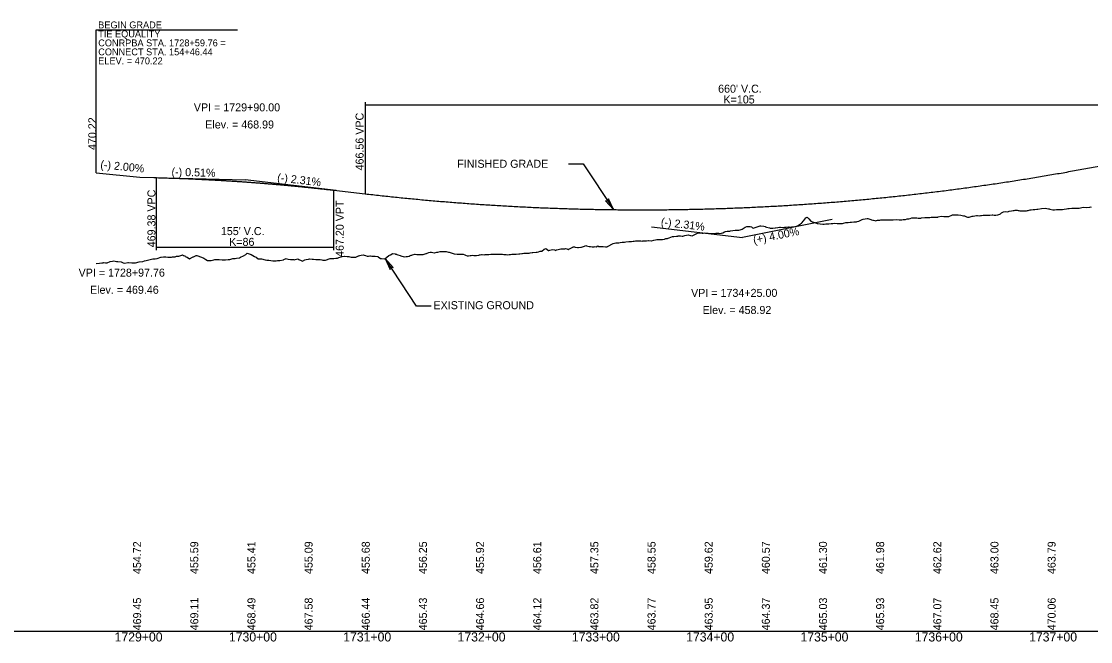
# Model space of a CAD drawing. Extents: x 2017200 to 2047700, y 854850 to 893350.
# Drawn here: x 2020794 to 2021730, y 874091 to 874634 of the extents above; entities that cross this region are included whole.
import ezdxf

# ---------------------------------------------------------------- set-up
doc = ezdxf.new("R2010")
doc.units = 0
for name, color, linetype in [('RD_DDB_GradeTX', 7, 'Continuous'), ('RD_DDB_Profile_EX', 7, 'Continuous'), ('RD_DDB_Profile_Lbl', 7, 'Continuous'), ('RD_DDB_Profile_PR', 7, 'Continuous'), ('RD_DDB_StaTX', 7, 'Continuous'), ('RD_DDB_StripGrade', 7, 'Continuous'), ('RD_DDB_VCLbl', 7, 'Continuous'), ('RD_GPK_Profile_Cell', 7, 'Continuous')]:
    doc.layers.add(name, color=color, linetype=linetype)

msp = doc.modelspace()

# ---------------------------------------------------------------- linework, layer by layer
at = {"layer": 'RD_DDB_GradeTX'}
for p, q in [((2020910.03, 874496.99), (2020990, 874494.95)), ((2021069.47, 874485.75), (2020990, 874494.95)), ((2021503.45, 874460.29), (2021425, 874444.6)), ((2021345.53, 874453.8), (2021425, 874444.6))]:
    msp.add_line(p, q, dxfattribs=at)
at = {"layer": 'RD_DDB_Profile_EX'}
msp.add_lwpolyline([(2020859.76, 874421.68), (2020862.53, 874422.1), (2020864.66, 874422.29), (2020865.68, 874422.32), (2020866.2, 874422.55), (2020867.82, 874422.35), (2020868.83, 874422.45), (2020869.32, 874422.53), (2020871.99, 874423.55), (2020873.98, 874423.83), (2020875.14, 874424.15), (2020877.58, 874423.61), (2020878.29, 874423.52), (2020878.64, 874423.49), (2020881.45, 874423.12), (2020883.3, 874422.28), (2020884.6, 874422.09), (2020887.34, 874422.63), (2020887.95, 874422.77), (2020890.91, 874422.53), (2020892.61, 874422.44), (2020894.06, 874422.4), (2020897.27, 874423.16), (2020900.37, 874423.67), (2020901.93, 874424.27), (2020903.52, 874424.39), (2020906.85, 874425.18), (2020909.1, 874425.75), (2020909.83, 874425.95), (2020911.25, 874425.93), (2020912.98, 874426.06), (2020916.13, 874427.25), (2020916.61, 874427.33), (2020918.63, 874427.49), (2020919.29, 874427.65), (2020920.57, 874427.63), (2020922.44, 874427.41), (2020925.23, 874427.39), (2020925.59, 874427.42), (2020926.37, 874427.49), (2020928.75, 874427.63), (2020929.88, 874428.22), (2020931.9, 874428.16), (2020934.54, 874429.05), (2020935.05, 874429.28), (2020936.12, 874428.89), (2020937.7, 874428.33), (2020938.21, 874427.75), (2020939.2, 874427.2), (2020941.36, 874425.95), (2020943.86, 874427.31), (2020944.51, 874427.5), (2020944.85, 874427.7), (2020945.88, 874428.24), (2020947.23, 874428.76), (2020947.67, 874428.71), (2020948.52, 874428.64), (2020950.82, 874427.6), (2020953.18, 874426.76), (2020953.97, 874426.51), (2020955.64, 874425.39), (2020957.13, 874424.39), (2020957.84, 874424.37), (2020960.28, 874424.46), (2020962.5, 874425.11), (2020963.43, 874425.21), (2020965.4, 874425.3), (2020966.59, 874425.26), (2020967.16, 874425.25), (2020969.74, 874424.89), (2020971.81, 874424.9), (2020972.89, 874424.89), (2020975.16, 874425.24), (2020976.05, 874425.32), (2020976.47, 874425.42), (2020979.2, 874426.05), (2020981.13, 874426.23), (2020982.35, 874426.45), (2020984.91, 874426.9), (2020985.79, 874427.22), (2020988.66, 874428.58), (2020990.45, 874429.54), (2020991.81, 874430.7), (2020995.11, 874429.69), (2020998.12, 874427.87), (2020999.77, 874427.23), (2021001.27, 874426.01), (2021004.43, 874425.85), (2021007.58, 874425.15), (2021009.09, 874424.75), (2021010.73, 874424.77), (2021014.19, 874424.25), (2021017.04, 874424.19), (2021018.4, 874424.29), (2021020.19, 874424.5), (2021023.49, 874425.04), (2021023.94, 874425.27), (2021025.88, 874426.07), (2021026.5, 874425.86), (2021027.72, 874425.6), (2021029.65, 874425.27), (2021032.38, 874425.19), (2021032.81, 874425.12), (2021033.7, 874425.39), (2021035.96, 874425.81), (2021037.04, 874425.34), (2021039.11, 874424.32), (2021040.18, 874423.76), (2021042.27, 874425.09), (2021043.46, 874425.44), (2021045.42, 874425.58), (2021046.36, 874425.81), (2021048.57, 874425.66), (2021049.71, 874425.51), (2021051.73, 874425.25), (2021052.17, 874425.24), (2021053.21, 874425.22), (2021054.88, 874425.2), (2021055.69, 874425.17), (2021057.09, 874424.89), (2021058.04, 874424.7), (2021059.55, 874424.78), (2021060.42, 874424.83), (2021061.21, 874424.98), (2021062.02, 874425.27), (2021062.75, 874425.53), (2021064.48, 874426.15), (2021065.21, 874426.08), (2021066.94, 874426.07), (2021067.55, 874426.06), (2021069.4, 874426.34), (2021070.07, 874426.44), (2021070.72, 874426.5), (2021071.94, 874426.98), (2021073.9, 874427.78), (2021074.33, 874427.85), (2021074.99, 874427.95), (2021076.79, 874428.19), (2021077.09, 874428.23), (2021079.25, 874427.98), (2021079.97, 874427.9), (2021080.28, 874427.8), (2021080.82, 874427.82), (2021081.71, 874427.59), (2021082.77, 874427.31), (2021083.48, 874427.35), (2021084.18, 874427.4), (2021085.03, 874427.46), (2021086.68, 874427.39), (2021089.1, 874428.43), (2021089.43, 874428.57), (2021090.17, 874428.83), (2021091.56, 874429.13), (2021093.1, 874429.45), (2021094.03, 874429.13), (2021095.38, 874428.66), (2021096.73, 874428.26), (2021097.79, 874428.32), (2021099.04, 874428.38), (2021099.54, 874428.44), (2021100.67, 874428.28), (2021101.41, 874428.27), (2021102.76, 874428.25), (2021103.87, 874428.14), (2021106, 874427.96), (2021106.34, 874427.71), (2021108.28, 874426.29), (2021108.8, 874426.19), (2021109.24, 874426.11), (2021111.53, 874425.9), (2021112.48, 874426.14), (2021113.83, 874427.32), (2021115.73, 874428.94), (2021116.19, 874429.09), (2021117.1, 874429.39), (2021118.65, 874430.29), (2021118.99, 874430.49), (2021121.11, 874430.12), (2021121.55, 874430.04), (2021122.25, 874429.88), (2021122.77, 874429.77), (2021123.57, 874429.47), (2021125.52, 874428.75), (2021126.04, 874428.6), (2021129.1, 874427.74), (2021130.96, 874427.83), (2021132.07, 874427.89), (2021133.42, 874428.33), (2021134.44, 874428.66), (2021135.36, 874429.02), (2021135.88, 874429.16), (2021136.47, 874429.32), (2021138.35, 874429.94), (2021138.65, 874430.04), (2021140.24, 874429.73), (2021140.81, 874429.72), (2021141.95, 874429.69), (2021143.27, 874429.73), (2021143.7, 874429.74), (2021145.25, 874429.66), (2021145.73, 874429.8), (2021146.61, 874430.06), (2021148.2, 874430.55), (2021148.57, 874430.66), (2021149.27, 874430.95), (2021150.77, 874431.53), (2021151.89, 874431.83), (2021153.12, 874431.59), (2021155.21, 874431.01), (2021155.58, 874431.1), (2021157.71, 874431.59), (2021158.04, 874431.62), (2021158.55, 874431.66), (2021160.52, 874432.35), (2021161.89, 874432.18), (2021162.97, 874432.27), (2021164.52, 874432.4), (2021165.43, 874432.36), (2021165.94, 874432.27), (2021167.89, 874431.85), (2021168.59, 874431.7), (2021170.36, 874431.05), (2021171.21, 874430.73), (2021171.95, 874430.47), (2021172.82, 874430.34), (2021175.32, 874430.01), (2021177.78, 874430), (2021178.7, 874430.02), (2021180.21, 874429.95), (2021180.61, 874429.93), (2021182.09, 874429.42), (2021182.67, 874429.21), (2021184.25, 874428.61), (2021185.13, 874428.47), (2021185.48, 874428.42), (2021186.88, 874428.75), (2021187.59, 874428.87), (2021188.88, 874429.09), (2021190.05, 874428.91), (2021190.61, 874428.82), (2021192.52, 874428.86), (2021194.29, 874429.16), (2021194.98, 874429.29), (2021195.71, 874429.43), (2021196.88, 874429.55), (2021197.44, 874429.55), (2021199.14, 874429.53), (2021199.9, 874429.59), (2021201.96, 874429.75), (2021202.57, 874429.77), (2021203.05, 874429.79), (2021204.83, 874429.9), (2021206.02, 874429.98), (2021207.29, 874429.98), (2021209.14, 874429.99), (2021209.92, 874429.97), (2021212.21, 874429.93), (2021212.93, 874429.91), (2021214.68, 874429.85), (2021215.14, 874429.83), (2021216.4, 874429.8), (2021217.14, 874429.71), (2021218.2, 874429.59), (2021219.88, 874429.45), (2021221.06, 874429.65), (2021222.06, 874429.82), (2021223.38, 874430.03), (2021224.53, 874429.99), (2021226.99, 874429.91), (2021229.45, 874430.19), (2021230.39, 874430.3), (2021231.91, 874430.5), (2021232.67, 874430.59), (2021233.9, 874430.8), (2021234.38, 874430.8), (2021235.89, 874430.81), (2021236.84, 874430.84), (2021237.43, 874430.87), (2021238.37, 874430.97), (2021239.3, 874431.13), (2021240.97, 874431.42), (2021241.76, 874431.45), (2021244.52, 874431.75), (2021245.44, 874431.85), (2021246.69, 874432.15), (2021248.09, 874432.5), (2021249.15, 874432.67), (2021249.57, 874432.74), (2021251.66, 874434.22), (2021253.01, 874435.01), (2021254.07, 874434.13), (2021255.24, 874433.28), (2021255.56, 874433.31), (2021256.54, 874433.55), (2021259, 874434.1), (2021260.51, 874433.85), (2021261.67, 874433.28), (2021262.44, 874433.74), (2021263.92, 874434.11), (2021266.06, 874434.57), (2021266.38, 874434.61), (2021268.85, 874434.66), (2021269.68, 874434.68), (2021270.31, 874435.01), (2021271.31, 874434.51), (2021272.47, 874433.99), (2021273.32, 874434.5), (2021273.77, 874434.74), (2021276.51, 874436.19), (2021276.98, 874436.28), (2021278.07, 874436.26), (2021278.7, 874436.18), (2021280.64, 874435.93), (2021281.16, 874435.9), (2021281.73, 874435.86), (2021283.62, 874436.12), (2021284.32, 874436.22), (2021286.08, 874436.77), (2021286.9, 874437.02), (2021288.01, 874437.42), (2021288.55, 874437.27), (2021291.01, 874436.63), (2021291.71, 874436.6), (2021292.02, 874436.59), (2021293.47, 874436.5), (2021295.43, 874436.37), (2021296.14, 874436.61), (2021297.1, 874436.46), (2021298.39, 874437.22), (2021299.16, 874436.75), (2021300.86, 874436.7), (2021302.13, 874436.66), (2021302.9, 874436.65), (2021303.32, 874436.6), (2021305.23, 874436.41), (2021305.78, 874436.43), (2021306.66, 874436.46), (2021307.12, 874436.6), (2021308.24, 874437.3), (2021310.71, 874438.74), (2021312.06, 874439.2), (2021313.17, 874439.57), (2021314.22, 874439.91), (2021315.63, 874439.95), (2021316.96, 874439.98), (2021318.09, 874440.09), (2021319.69, 874440.48), (2021320.55, 874440.51), (2021321.85, 874440.55), (2021323.02, 874440.69), (2021325.66, 874441), (2021326.65, 874440.92), (2021327.94, 874441.07), (2021329.51, 874441.24), (2021330.4, 874441.41), (2021331.43, 874441.6), (2021332.87, 874441.61), (2021333.37, 874441.62), (2021335.33, 874441.54), (2021336.18, 874441.5), (2021337.25, 874441.48), (2021337.79, 874441.51), (2021340.25, 874441.65), (2021341.14, 874441.71), (2021342.71, 874441.88), (2021343.16, 874441.93), (2021345.18, 874441.7), (2021345.57, 874441.71), (2021347.64, 874442.17), (2021348.98, 874442.47), (2021350.21, 874442.82), (2021352.56, 874442.9), (2021352.93, 874442.92), (2021355.03, 874442.79), (2021356.89, 874442.97), (2021357.49, 874443.3), (2021358.06, 874443.62), (2021359.4, 874443.71), (2021359.95, 874443.97), (2021360.87, 874444.39), (2021362.41, 874444.93), (2021363.95, 874445.46), (2021364.88, 874445.41), (2021367.34, 874445.69), (2021368.46, 874445.81), (2021368.89, 874445.9), (2021369.8, 874445.99), (2021370.81, 874446.09), (2021372.26, 874445.79), (2021372.95, 874445.65), (2021374.72, 874446.23), (2021377.4, 874447.01), (2021379.65, 874446.45), (2021381.06, 874446.1), (2021382.11, 874446.49), (2021384.57, 874447.84), (2021385.16, 874448.16), (2021386.23, 874448.5), (2021387.04, 874448.54), (2021389.5, 874448.57), (2021389.92, 874448.45), (2021390.6, 874448.35), (2021392.05, 874448.63), (2021393.42, 874448.39), (2021394.42, 874448.31), (2021394.95, 874448.26), (2021396.88, 874448.15), (2021397.58, 874448.11), (2021399.35, 874448.06), (2021401.81, 874448.25), (2021403.57, 874448.31), (2021404.27, 874448.22), (2021405.97, 874448), (2021406.73, 874448.28), (2021407.84, 874448.67), (2021409.2, 874449.54), (2021410.2, 874449.76), (2021411.66, 874450), (2021412.09, 874450.07), (2021414.12, 874450.23), (2021414.45, 874450.26), (2021416.58, 874450.54), (2021418.73, 874450.86), (2021419.05, 874450.89), (2021420.51, 874451.01), (2021421.75, 874451.05), (2021423.03, 874451.36), (2021423.97, 874451.69), (2021424.69, 874451.94), (2021426.43, 874453.09), (2021427.36, 874453.7), (2021428.89, 874454.25), (2021431.36, 874454.06), (2021431.72, 874454.04), (2021432.98, 874453.76), (2021433.82, 874453.16), (2021434.49, 874452.68), (2021436.28, 874453.36), (2021437.09, 874453.51), (2021438.74, 874454.11), (2021440.5, 874454.75), (2021441.21, 874454.85), (2021443.67, 874454.33), (2021444.94, 874454.07), (2021445.25, 874453.96), (2021446.13, 874453.72), (2021448.59, 874453.05), (2021449.4, 874452.85), (2021451.05, 874452.84), (2021451.48, 874452.84), (2021453.52, 874452.98), (2021453.9, 874453.01), (2021455.98, 874453.33), (2021457.35, 874453.55), (2021458.44, 874453.6), (2021460.9, 874453.33), (2021461.35, 874453.29), (2021462.11, 874453.55), (2021462.97, 874453.66), (2021463.37, 874453.68), (2021465.32, 874453.79), (2021465.83, 874453.75), (2021467.56, 874453.63), (2021468.29, 874453.77), (2021469.28, 874453.96), (2021470.75, 874454.26), (2021472.18, 874454.55), (2021473.22, 874454.91), (2021475.68, 874456.42), (2021476.83, 874457.12), (2021477.15, 874457.54), (2021478.14, 874458.75), (2021478.76, 874459.5), (2021480.6, 874461.66), (2021481.52, 874462.41), (2021483.06, 874460.8), (2021484.94, 874458.85), (2021485.53, 874458.53), (2021486.24, 874458.15), (2021487.99, 874457.69), (2021488.82, 874457.47), (2021490.45, 874456.93), (2021491, 874456.75), (2021492.91, 874456.49), (2021495.38, 874456.34), (2021495.79, 874456.32), (2021496.52, 874456.28), (2021497.84, 874456.37), (2021499.29, 874456.47), (2021500.62, 874456.55), (2021502.76, 874456.78), (2021504.15, 874456.94), (2021505.5, 874456.96), (2021507.95, 874456.9), (2021510.41, 874456.91), (2021511.16, 874456.83), (2021511.73, 874456.73), (2021512.61, 874456.94), (2021513.3, 874457.11), (2021515.5, 874457.6), (2021515.91, 874457.63), (2021517.54, 874457.81), (2021519.25, 874458), (2021520, 874458.05), (2021520.36, 874458.07), (2021522.46, 874458.2), (2021522.99, 874458.23), (2021524.92, 874458.41), (2021525.41, 874458.45), (2021526.72, 874458.79), (2021527.39, 874459.11), (2021529.85, 874460.31), (2021530.5, 874460.61), (2021532.31, 874460.93), (2021534.13, 874461.25), (2021534.77, 874461.1), (2021535.63, 874460.9), (2021537.23, 874460.33), (2021537.82, 874460.12), (2021539.06, 874459.7), (2021539.7, 874459.63), (2021540.82, 874459.5), (2021541.49, 874459.27), (2021542.16, 874459.42), (2021543.07, 874459.62), (2021544.62, 874459.79), (2021545.15, 874459.85), (2021546.06, 874459.89), (2021547.08, 874459.89), (2021548.8, 874459.9), (2021549.55, 874459.92), (2021551.35, 874459.95), (2021552.01, 874459.97), (2021552.44, 874459.98), (2021554.77, 874459.98), (2021556.07, 874459.98), (2021556.93, 874460.05), (2021559.68, 874460.17), (2021562.09, 874460.03), (2021563.28, 874460.08), (2021564.32, 874460.16), (2021565.58, 874460.26), (2021567.14, 874460.37), (2021567.55, 874460.43), (2021569.24, 874460.75), (2021570.45, 874460.97), (2021571.71, 874461.29), (2021573.07, 874461.64), (2021574.17, 874461.77), (2021575.71, 874461.75), (2021576.63, 874461.77), (2021577.58, 874461.79), (2021578.65, 874461.58), (2021579.09, 874461.59), (2021581.13, 874461.62), (2021581.55, 874461.67), (2021584.66, 874462.01), (2021585.25, 874462.04), (2021586.48, 874462.08), (2021588.19, 874462.12), (2021588.94, 874462.17), (2021590.02, 874462.25), (2021591.4, 874462.31), (2021591.71, 874462.32), (2021593.87, 874462.26), (2021594.31, 874462.25), (2021595.21, 874462.32), (2021595.81, 874462.46), (2021596.33, 874462.61), (2021598.79, 874463.26), (2021601.25, 874462.9), (2021601.67, 874462.84), (2021602.2, 874462.8), (2021602.95, 874462.8), (2021603.72, 874462.83), (2021605.68, 874462.9), (2021606.18, 874463.14), (2021607.62, 874463.83), (2021608.64, 874464.29), (2021609.15, 874464.52), (2021611.23, 874464.44), (2021612.61, 874464.37), (2021613.64, 874464.29), (2021616.06, 874464.15), (2021618.49, 874463.56), (2021619.18, 874463.39), (2021619.75, 874463.22), (2021620.95, 874462.71), (2021621.79, 874462.35), (2021622.93, 874462.33), (2021623.41, 874462.46), (2021625.95, 874463.12), (2021626.36, 874463.23), (2021626.85, 874463.25), (2021628.34, 874463.53), (2021629.77, 874463.8), (2021630.8, 874463.73), (2021632.24, 874463.62), (2021633.26, 874463.71), (2021634.27, 874463.89), (2021635.72, 874463.99), (2021636.58, 874464.05), (2021638.19, 874464.18), (2021638.63, 874464.22), (2021639.97, 874464.15), (2021640.65, 874464.18), (2021641.45, 874464.21), (2021643.36, 874464.36), (2021643.96, 874464.37), (2021645.12, 874464.19), (2021645.57, 874464.15), (2021646.73, 874464.05), (2021648.04, 874464.38), (2021648.43, 874464.48), (2021650.1, 874465.05), (2021650.65, 874465.21), (2021651.73, 874466.06), (2021652.96, 874466.72), (2021653.46, 874466.99), (2021655.42, 874467.27), (2021656.82, 874467.09), (2021657.89, 874467.34), (2021658.45, 874467.47), (2021660.35, 874467.81), (2021661.81, 874468.07), (2021662.81, 874468.27), (2021663.5, 874468.41), (2021665.29, 874468.34), (2021666.33, 874468.28), (2021666.83, 874468.21), (2021667.73, 874468), (2021668.58, 874467.8), (2021670.2, 874467.89), (2021670.83, 874467.94), (2021672.27, 874467.81), (2021672.66, 874467.83), (2021673.47, 874467.86), (2021674.54, 874468.08), (2021675.12, 874468.24), (2021676.78, 874468.69), (2021677.58, 874468.79), (2021679.38, 874469), (2021680.09, 874469.06), (2021680.69, 874469.13), (2021682.51, 874469.33), (2021683.39, 874469.43), (2021686.74, 874470), (2021689.98, 874470.12), (2021692.78, 874469.59), (2021693.27, 874469.5), (2021693.87, 874469.35), (2021696.57, 874468.82), (2021697.99, 874468.88), (2021699.87, 874468.93), (2021701.12, 874468.98), (2021703.16, 874469.05), (2021704.87, 874469.11), (2021706.46, 874469.24), (2021708.37, 874469.63), (2021709.75, 874469.9), (2021710.91, 874469.83), (2021713.05, 874470.09), (2021715.62, 874470.25), (2021716.35, 874470.36), (2021716.95, 874470.32), (2021719.64, 874470.24), (2021723, 874471.2), (2021726.23, 874470.92), (2021729.04, 874471.2), (2021729.53, 874471.25), (2021730.12, 874471.21)], dxfattribs=at)
at = {"layer": 'RD_DDB_Profile_Lbl'}
for p, q in [((2021139.94, 874384.43), (2021112.48, 874426.14)), ((2021152.8, 874384.43), (2021139.94, 874384.43))]:
    msp.add_line(p, q, dxfattribs=at)
for points in [[(2020859.76, 874501.1), (2020859.76, 874626.27), (2020983.31, 874626.27)], [(2021272.87, 874509.12), (2021285.73, 874509.12), (2021312.18, 874468.94)]]:
    msp.add_lwpolyline(points, dxfattribs=at)
for points in [[(2021312.18, 874468.94), (2021307.72, 874478.44), (2021307.35, 874476.28), (2021305.22, 874476.79)], [(2021112.48, 874426.14), (2021116.94, 874416.64), (2021117.31, 874418.8), (2021119.44, 874418.29)]]:
    msp.add_lwpolyline(points, close=True, dxfattribs=at)
at = {"layer": 'RD_DDB_Profile_PR'}
for p, q in [((2020859.76, 874501.1), (2020897.76, 874497.3)), ((2020897.76, 874497.3), (2020912.5, 874496.92)), ((2021067.5, 874485.98), (2021095, 874482.8))]:
    msp.add_line(p, q, dxfattribs=at)
for points in [[(2021095, 874482.8), (2021108.2, 874481.31), (2021121.4, 874479.91), (2021134.6, 874478.59), (2021147.8, 874477.35), (2021161, 874476.2), (2021174.2, 874475.13), (2021187.4, 874474.14), (2021200.6, 874473.24), (2021213.8, 874472.42), (2021227, 874471.69), (2021240.2, 874471.03), (2021253.4, 874470.46), (2021266.6, 874469.98), (2021279.8, 874469.58), (2021293, 874469.26), (2021306.2, 874469.02), (2021319.4, 874468.87), (2021332.6, 874468.8), (2021345.8, 874468.81), (2021359, 874468.91), (2021372.2, 874469.09), (2021385.4, 874469.36), (2021398.6, 874469.7), (2021411.8, 874470.13), (2021425, 874470.65), (2021438.2, 874471.25), (2021451.4, 874471.93), (2021464.6, 874472.69), (2021477.8, 874473.54), (2021491, 874474.47), (2021504.2, 874475.49), (2021517.4, 874476.58), (2021530.6, 874477.77), (2021543.8, 874479.03), (2021557, 874480.38), (2021570.2, 874481.81), (2021583.4, 874483.32), (2021596.6, 874484.92), (2021609.8, 874486.6), (2021623, 874488.37), (2021636.2, 874490.22), (2021649.4, 874492.15), (2021662.6, 874494.16), (2021675.8, 874496.26), (2021689, 874498.44), (2021702.2, 874500.71), (2021715.4, 874503.06), (2021728.6, 874505.49), (2021741.8, 874508), (2021755, 874510.6)], [(2020912.5, 874496.92), (2020915.6, 874496.84), (2020918.7, 874496.76), (2020921.8, 874496.66), (2020924.9, 874496.56), (2020928, 874496.46), (2020931.1, 874496.35), (2020934.2, 874496.23), (2020937.3, 874496.11), (2020940.4, 874495.99), (2020943.5, 874495.85), (2020946.6, 874495.72), (2020949.7, 874495.57), (2020952.8, 874495.42), (2020955.9, 874495.27), (2020959, 874495.11), (2020962.1, 874494.94), (2020965.2, 874494.77), (2020968.3, 874494.6), (2020971.4, 874494.41), (2020974.5, 874494.23), (2020977.6, 874494.03), (2020980.7, 874493.83), (2020983.8, 874493.63), (2020986.9, 874493.42), (2020990, 874493.2), (2020993.1, 874492.98), (2020996.2, 874492.75), (2020999.3, 874492.52), (2021002.4, 874492.28), (2021005.5, 874492.04), (2021008.6, 874491.79), (2021011.7, 874491.53), (2021014.8, 874491.27), (2021017.9, 874491), (2021021, 874490.73), (2021024.1, 874490.45), (2021027.2, 874490.17), (2021030.3, 874489.88), (2021033.4, 874489.59), (2021036.5, 874489.29), (2021039.6, 874488.98), (2021042.7, 874488.67), (2021045.8, 874488.35), (2021048.9, 874488.03), (2021052, 874487.7), (2021055.1, 874487.37), (2021058.2, 874487.03), (2021061.3, 874486.69), (2021064.4, 874486.34), (2021067.5, 874485.98)]]:
    msp.add_spline(points, degree=3, dxfattribs=at)
at = {"layer": 'RD_DDB_VCLbl'}
for p, q in [((2021095, 874563.1), (2021095, 874482.8)), ((2021095, 874560.6), (2021755, 874560.6)), ((2020912.5, 874433.48), (2020912.5, 874496.92)), ((2021067.5, 874433.48), (2021067.5, 874485.98)), ((2020912.5, 874435.98), (2021067.5, 874435.98))]:
    msp.add_line(p, q, dxfattribs=at)
at = {"layer": 'RD_GPK_Profile_Cell'}
msp.add_line((2020500, 874100), (2023600, 874100), dxfattribs=at)

# ---------------------------------------------------------------- texts
at = {"layer": 'RD_DDB_GradeTX'}
for s, rotation, p in [('(-) 2.00%', 354.28924, (2020863.07, 874505.17)), ('(-) 0.51%', 358.54057, (2020925.48, 874498.59)), ('(-) 2.31%', 353.39756, (2021017.73, 874493.75)), ('(-) 2.31%', 353.39756, (2021353.39, 874454.9)), ('(+) 4.00%', 11.30993, (2021435.09, 874438.83))]:
    msp.add_text(s, height=7, rotation=rotation, dxfattribs=at).set_placement(p)
at = {"layer": 'RD_DDB_Profile_Lbl'}
for s, height, p in [('BEGIN GRADE', 6, (2020861.44, 874627.61)), ('TIE EQUALITY', 6, (2020861.44, 874619.74)), ('CONRPBA STA. 1728+59.76 =', 6, (2020861.44, 874611.87)), ('CONNECT STA. 154+46.44', 6, (2020861.44, 874604)), ('ELEV. = 470.22', 6, (2020861.44, 874596.14)), ('VPI = 1729+90.00', 7, (2020945.1, 874554.95)), ('Elev. = 468.99', 7, (2020955.11, 874539.95)), ('FINISHED GRADE', 7, (2021175.55, 874505.57)), ('VPI = 1728+97.76', 7, (2020844.28, 874410.31)), ('Elev. = 469.46', 7, (2020854.29, 874395.31)), ('VPI = 1734+25.00', 7, (2021380.1, 874392.6)), ('EXISTING GROUND', 7, (2021154.74, 874381.81)), ('Elev. = 458.92', 7, (2021390.19, 874377.6))]:
    msp.add_text(s, height=height, dxfattribs=at).set_placement(p)
msp.add_text('470.22', height=7, rotation=90, dxfattribs=at).set_placement((2020859.76, 874521.1))
at = {"layer": 'RD_DDB_StaTX'}
for s, p in [('1729+00', (2020875.8, 874091)), ('1730+00', (2020975.8, 874091)), ('1731+00', (2021075.8, 874091)), ('1732+00', (2021175.8, 874091)), ('1733+00', (2021275.8, 874091)), ('1734+00', (2021375.8, 874091)), ('1735+00', (2021475.8, 874091)), ('1736+00', (2021575.8, 874091)), ('1737+00', (2021675.8, 874091))]:
    msp.add_text(s, height=8, dxfattribs=at).set_placement(p)
at = {"layer": 'RD_DDB_StripGrade'}
for s, p in [('466.56 VPC', (2021093.59, 874503.26)), ('469.38 VPC', (2020911.5, 874435.98)), ('467.20 VPT', (2021076.23, 874427.56)), ('454.72', (2020899, 874150)), ('455.59', (2020949, 874150)), ('455.41', (2020999, 874150)), ('455.09', (2021049, 874150)), ('455.68', (2021099, 874150)), ('456.25', (2021149, 874150)), ('455.92', (2021199, 874150)), ('456.61', (2021249, 874150)), ('457.35', (2021299, 874150)), ('458.55', (2021349, 874150)), ('459.62', (2021399, 874150)), ('460.57', (2021449, 874150)), ('461.30', (2021499, 874150)), ('461.98', (2021549, 874150)), ('462.62', (2021599, 874150)), ('463.00', (2021649, 874150)), ('463.79', (2021699, 874150)), ('469.45', (2020899, 874100.75)), ('469.11', (2020949, 874100.75)), ('468.49', (2020999, 874100.75)), ('467.58', (2021049, 874100.75)), ('466.44', (2021099, 874100.75)), ('465.43', (2021149, 874100.75)), ('464.66', (2021199, 874100.75)), ('464.12', (2021249, 874100.75)), ('463.82', (2021299, 874100.75)), ('463.77', (2021349, 874100.75)), ('463.95', (2021399, 874100.75)), ('464.37', (2021449, 874100.75)), ('465.03', (2021499, 874100.75)), ('465.93', (2021549, 874100.75)), ('467.07', (2021599, 874100.75)), ('468.45', (2021649, 874100.75)), ('470.06', (2021699, 874100.75))]:
    msp.add_text(s, height=7, rotation=90, dxfattribs=at).set_placement(p)
at = {"layer": 'RD_DDB_VCLbl'}
for s, p in [("660' V.C.", (2021403.75, 874571.28)), ('K=105', (2021408.42, 874561.85)), ("155' V.C.", (2020968.75, 874446.66)), ('K=86', (2020975.99, 874437.23))]:
    msp.add_text(s, height=7, dxfattribs=at).set_placement(p)

doc.saveas('drawing.dxf')
